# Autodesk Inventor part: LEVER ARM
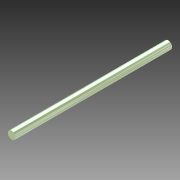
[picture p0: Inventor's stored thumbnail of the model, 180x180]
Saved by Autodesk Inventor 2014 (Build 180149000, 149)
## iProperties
Shininess: 64.0
Length Units: 11272
Angle Units: 11279
Time Units: 11290
Mass Units: 11286
Length Display Precision: 3
Angle Display Precision: 2
Compacted: True
Part Number: LEVER ARM
Document SubType Name: Modeling
Created: 2003-11
Designer: Autodesk, Inc.
Manufacturer: Standard
Standards Organization: Custom
Mass: 252.903 g
Surface Area: 103.875 cm^2
Volume: 32.1759 cm^3
Density: 7.86 g/cm^3
Material: Steel, Mild
Appearance: Nickel (Bright)
Density: 0.0
Volumn: 0.0
Area: 0.0
PropertySet Name: Model Information
Control State: 0
Master: False
Checked Out: False
Author: Autodesk, Inc.
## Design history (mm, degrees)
sketch "Sketch1"
  geometry: C1 r 6.35 at (0, 0); 1 further point
  constraints: 1 centre point, 1 coincident
  dimensions: "d0" = 12.7 diameter of C1
extrude "Extrusion1" new body sketch "Sketch1" distance "d1" = 254; taper "d2" = 0 deg
workplane "Work Plane1"
body "Solid1"
